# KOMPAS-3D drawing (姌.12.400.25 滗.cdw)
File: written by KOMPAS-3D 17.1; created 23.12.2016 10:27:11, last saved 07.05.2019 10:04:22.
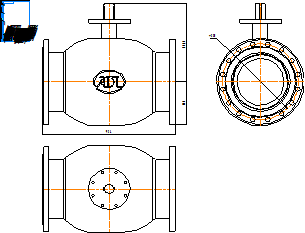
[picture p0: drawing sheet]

Sheet 1: A4, portrait

Title block, sheet 1: name: КШ.12.400.25 фф; material: Внимание! Данный продукт является объектом авторского права ООО «Торговый Дом АДЛ». / Запрещается изменение, копирование, распространение / (в том числе путем копирования на другие сайты и ресурсы в Интернете) / или любое иное использование информации и объектов без предварительного / согласия правообладателя (ООО «Торговый Дом АДЛ»).; sheets: 1; organisation: ООО "Торговый дом АДЛ"; sheet format: A4; stored path: C:\Users\tra\Desktop\2д чертежи\Шаровые краны БИВАЛ\КШ_Бивал_серия_11_12\KOMPAS_2D\КШ.12.400.25 фф.cdw

Views: Вид 1, Проекционный вид 2, Проекционный вид 3
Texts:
  Klimkovich
  ADL
Dimensions and other numbers on the sheet: 956; 564,5; 305; 550; 1:1; 1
